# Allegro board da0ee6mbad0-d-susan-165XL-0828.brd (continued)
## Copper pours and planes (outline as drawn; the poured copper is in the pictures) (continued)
GND on IN3 (solid shape): 105.07,56.59 105.7,55.96 105.7,53.9 105.3,53.5 101.39,53.5 99.24,51.35 99.21,51.33 99.19,51.33 99.16,51.33 99.14,51.35 99.12,51.37 99.11,51.54 102.92,55.35 102.92,57.48 103.09,57.48 103.09,57.13 103.12,57.09 103.12,56.69 103.37,56.45 103.71,56.45 103.79,56.53 103.87,56.45 104.21,56.45 104.46,56.69 104.46,57.08 104.5,57.13 104.5,57.48 104.26,57.72 103.91,57.72 103.88,57.69 103.71,57.69 103.67,57.72 103.33,57.72 103.09,57.48 102.92,57.48 102.92,58.08 102.92,58.09 102.93,58.13 102.95,58.16 102.97,58.18 102.99,58.2 103.02,58.22 103.06,58.23 103.09,58.23 103.14,58.22 103.2,58.22 103.26,58.22 103.32,58.23 103.38,58.26 103.44,58.28 103.49,58.32 103.53,58.36 103.57,58.41 103.61,58.46 103.63,58.52 103.65,58.58 103.66,58.64 103.66,58.82 105.07,58.82
GND on IN3 (solid shape): 49.03,57.15 49.12,57.18 49.22,57.15 49.29,57.11 49.37,57.09 49.4,57.09 49.47,57.01 49.47,56.57 49.91,56.12 49.96,56.02 49.91,55.91 49.81,55.68 49.88,55.43 49.88,54.74 49.79,54.6 49.62,54.64 49.36,54.75 49.09,54.65 48.76,54.65 48.76,54.78 49.18,55.2 49.18,56 49.18,56.01 49.18,56.46 49.03,56.61
GND on IN3 (solid shape): 25.02,54.79 25.11,54.94 25.28,54.9 26.23,53.94 26.36,53.94 26.36,53.85 26.35,53.83 26.35,53.41 26.74,53.25 26.75,53.25 26.83,53.25 26.83,53.09 26.77,53.08 26.46,52.73 26.77,52.38 26.83,52.37 26.83,50.06 26.94,49.84 27.18,49.79 27.19,49.79 27.27,49.79 27.27,49.63 27,49.36 26.98,49.35 26.89,49.3 26.82,49.21 26.71,49.12 26.57,49.17 25.02,50.72
GND on IN3 (solid shape): 40.6,81.07 40.73,80.98 40.71,80.81 41.02,80.14 41.32,80.81 41.3,80.98 41.44,81.07 41.63,81.07 41.75,81 41.77,80.87 42.16,80.34 42.55,80.87 42.57,81 42.7,81.07 44.56,81.07 44.85,80.78 44.85,79.57 44.47,79.19 43.49,79.19 43.45,79.23 38.58,79.23 38.17,79.64 38.17,80.78 38.45,81.07
GND on IN3 (solid shape): 68.26,70.29 68.26,69.46 67.79,68.99 66.6,68.99 66.6,69.28 66.43,69.45 63.61,69.45 63.42,69.25 63.42,68.18 63.14,67.9 62.15,67.9 61.84,67.59 61.52,67.59 61.47,67.64 61.33,67.64 60.96,67.68 60.75,67.37 60.73,67.31 60.68,67.29 60.58,67.29 60.58,67.39 60.24,67.74 59.87,67.43 59.86,67.36 58.95,67.36 58.95,67.52 58.99,67.62 59.32,67.78 59.41,68.02 59.41,68.58 59.39,68.69 59.34,68.8 59.32,68.96 59.46,69.04 60.27,69.04 60.27,68.96 60.46,68.65 60.83,68.67 60.85,68.68 60.92,68.68 60.97,68.63 61.2,68.63 61.36,68.8 61.36,68.9 61.98,68.9 62.18,68.7 62.53,68.7 62.77,68.94 62.77,69.29 62.65,69.41 62.8,69.55 62.8,69.9 62.55,70.14 62.51,70.14 62.25,70.39 62.25,70.64 62.38,70.77 67.79,70.77
GND on IN3 (solid shape): 30.77,75.49 30.99,75.28 32.53,75.28 32.74,75.49 32.74,75.54 32.96,75.54 32.96,75.33 32.89,75.26 32.86,75.26 32.56,74.88 32.92,74.55 33.42,74.55 33.51,74.56 33.6,74.59 33.75,74.59 33.82,74.46 33.82,74.27 33.76,74.14 33.62,74.12 33.32,74.1 33.15,73.86 33.14,73.79 32.36,73.79 31.76,74.39 31.75,74.41 31.65,74.53 31.51,74.57 31.01,74.57 30.82,74.49 30.74,74.31 30.74,74.07 30.51,74.07 30.32,73.99 30.24,73.81 30.24,73.65 30.15,73.48 30.17,73.29 30.15,73.15 30.02,73.09 29.89,73.09 29.76,72.96 27.39,72.96 26.86,72.43 26.3,72.43 26.06,72.67 26.06,75.3 26.14,75.44 26.3,75.42 26.56,75.34 26.8,75.44 27.01,75.44 29.54,75.44 30.64,76.54 30.77,76.54
GND on IN3 (solid shape): 25.16,80.76 25.26,80.8 25.36,80.78 25.42,80.74 25.49,80.72 25.61,80.62 25.57,80.47 25.45,80.34 25.45,77.34 25.39,77.22 24.93,77.1 24.79,76.79 24.79,76.18 24.93,75.86 25.39,75.74 25.45,75.62 25.45,72.42 25.64,72.23 25.67,72.06 25.53,71.97 25.46,71.97 25.45,72.03 25.15,72.28 24.89,72 24.89,70.09 25.16,69.81 25.45,70.08 25.45,70.11 26.71,71.37 27.54,71.37 27.54,70.79 27.68,70.65 30.23,70.65 30.37,70.56 30.33,70.39 30.22,70.27 30.22,70.09 29.89,70.09 29.71,69.91 29.71,66.18 29.64,66.05 29.61,65.91 29.61,63.55 29.63,63.45 29.67,63.35 29.7,63.3 29.05,62.65 29.05,59.3 29.47,58.88 30.12,58.88 30.15,58.91 30.24,58.87 30.24,58.36 30.01,58.14 30.01,57.8 27.9,57.8 27.71,57.61 27.71,57.35 27.61,57.2 27.45,57.24 27.38,57.31 27.38,57.34 26.83,57.89 24.84,57.89 24.65,57.7 24.48,57.66 24.39,57.81 24.39,79.99
GND on IN3 (solid shape): outline of 397 points within 18.38,12.3 24.69,32.89
GND on IN3 (solid shape): outline of 644 points within 21.64,34.48 51.35,54.34
GND on IN3 (solid shape): outline of 3811 points within 0.51,0.51 175.29,87.42
GND on GND3 (solid shape): outline of 58666 points within 0.51,0.51 175.29,87.42
GND on IN4 (solid shape): 67.33,60.91 64.41,60.91 64.41,64.62 67.33,64.62
GND on IN4 (solid shape): 68.43,85.41 65.77,85.41 65.77,85.92 68.43,85.92
GND on IN4 (solid shape): 35.56,79.25 33.73,77.42 33.73,77.19 33.75,77.16 33.71,77.07 32.19,77.07 32.19,77.78 33.99,79.58 33.99,79.92 34.04,79.97 35.56,79.97
GND on IN4 (solid shape): 30.24,52.66 30.31,52.48 30.53,52.37 30.55,52.32 30.55,52.03 29.99,52.03 29.9,52.12 29.9,53.6 30.02,53.72 30.24,53.72
GND on IN4 (solid shape): 59.68,56.82 59.68,56.47 59.81,56.34 59.81,56.15 59.72,56.06 59.41,56.06 59.3,56.04 59.21,55.98 59.12,55.89 58.92,55.89 58.85,55.97 58.85,56.8 58.97,56.91 59.14,56.91 59.33,57.11 59.39,57.11
GND on IN4 (solid shape): 88.99,50.55 88.99,47.42 88.88,47.3 88.52,47.3 88.02,47.8 88.02,48.36 87.42,48.96 86.08,48.96 85.93,49.11 85.93,49.57 85.87,49.63 85.83,49.79 85.97,49.89 87.87,49.89 88.62,50.64 88.9,50.64
GND on IN4 (solid shape): 47.25,60.83 47.34,60.97 47.51,60.93 47.81,60.63 47.81,60.25 48.08,59.98 49.77,59.98 49.87,59.94 49.92,59.84 49.92,59.82 49.92,59.73 47.37,59.73 47.25,59.86
GND on IN4 (solid shape): 34.23,52.12 34.23,49.74 33.91,49.42 33.91,49.4 33.87,49.37 32.89,49.37 32.69,49.57 32.69,49.91 32.61,50.11 32.42,50.19 32.39,50.19 31.24,51.34 31.2,51.44 31.23,51.54 31.27,51.61 31.29,51.68 31.29,51.71 31.47,51.89 31.47,52.4 33.95,52.4
GND on IN4 (solid shape): 65.43,80.62 65.6,80.65 65.69,80.51 65.69,76.72 65.64,76.61 65.51,76.57 65.36,76.58 65.22,76.53 65.21,76.52 64.9,76.52 64.42,76.04 64.26,76.01 64.16,76.15 64.16,77.04 64.13,77.07 64.13,77.1 64.1,77.23 64,77.33 64,77.74 63.96,77.78 63.95,77.78 63.68,78.05 63.68,78.17 64,78.49 64,79.19
GND on IN4 (solid shape): 86.63,71.78 86.63,69.81 86.18,69.36 86.18,68.91 86.14,68.81 85.85,68.67 85.77,68.48 85.77,68.12 85.79,68.03 85.83,67.95 85.86,67.85 85.82,67.75 85.43,67.37 85.32,67.32 85.21,67.38 85.18,67.41 85.15,67.44 85.15,68.26 85.16,68.27 85.18,68.47 85.07,68.63 85.07,70.79 84.69,71.17 84.69,71.72 84.82,71.84 86.57,71.84
GND on IN4 (solid shape): 62.34,86.42 62.34,85.81 63.03,84.89 64.1,85.29 64.2,85.29 64.51,84.98 62.87,84.41 61.83,85.81 61.83,85.91 58.15,85.91 58.15,84.84 54.12,84.84 54.12,84.14 51.66,84.14 51.41,84.39 51.38,84.56 51.52,84.65 53.61,84.65 53.61,85.35 57.64,85.35 57.64,86.42 57.64,86.42 62.34,86.42
GND on IN4 (solid shape): outline of 129 points within 12.68,46.31 20.42,54.87
GND on IN4 (solid shape): 97.24,62.72 97.3,62.6 97.3,61.6 97.38,61.4 97.69,61.27 97.74,61.16 97.74,61.11 97.69,61.01 97.59,60.96 97.33,60.68 97.59,60.4 97.69,60.35 97.74,60.25 97.74,59.42 97.74,59.4 97.74,59.01 97.74,59 97.74,58.15 97.74,58.13 97.74,57.74 97.74,57.73 97.74,56.88 97.74,56.86 97.74,56.47 97.74,56.46 97.74,55.61 97.74,55.59 97.74,55.2 97.74,55.19 97.74,54.34 97.74,54.32 97.74,53.93 97.74,53.92 97.74,53.1 97.74,53.08 97.74,52.66 97.74,52.65 97.74,51.83 97.74,51.81 97.74,51.39 97.74,51.38 97.74,50.09 97.64,49.95 97.48,49.98 97.1,50.36 97.1,51.31 97.08,51.35 97.07,51.39 97.08,51.42 97.1,51.46 97.1,51.74 97.08,51.79 97.07,51.82 97.08,51.85 97.1,51.89 97.1,52.58 97.08,52.62 97.07,52.66 97.08,52.69 97.1,52.73 97.1,52.97 97.07,53.01 97.05,53.06 97.07,53.11 97.1,53.15 97.1,53.75 97.08,53.77 97.08,55.42 96.72,55.78 96.72,62.54 96.92,62.74 97.05,62.74 97.08,62.74 97.11,62.75
GND on IN4 (solid shape): 45.96,59.99 46.02,59.92 45.96,59.84 45.79,59.69 45.87,59.47 45.92,59.35 45.87,59.23 45.81,59.16 45.79,59.07 45.77,59.02 45.57,58.94 45.48,58.74 45.43,58.72 45.24,58.58 45.29,58.35 45.29,58.22 45.22,58.15 45.14,58.15 44.85,58.08 44.91,57.79 44.94,57.77 44.94,57.42 44.83,57.3 44.42,57.71 44.42,58.32 44.44,58.34 44.46,58.39 44.48,58.44 44.52,58.53 44.61,58.58 44.74,58.64 44.8,58.78 44.82,58.83 44.87,58.86 45.07,59 45,59.23 44.95,59.35 45,59.47 45.06,59.54 45.08,59.63 45.1,59.68 45.16,59.71 45.29,59.76 45.36,59.88 45.37,59.95 45.8,59.95 45.87,60.02
GND on IN4 (solid shape): outline of 176 points within 31.28,71.57 35.74,76.55
GND on IN4 (solid shape): outline of 197 points within 30.77,52.92 35.74,57.9
GND on IN4 (solid shape): 44.98,71.07 44.98,70.7 45.24,70.44 45.4,70.44 45.53,70.36 45.53,70.21 45.51,70.16 45.51,70.11 45.48,70.06 45.43,70.03 45.22,69.82 45.43,69.61 45.48,69.59 45.57,69.39 45.77,69.3 45.79,69.25 45.81,69.16 45.87,69.09 45.92,68.97 45.79,68.69 45.92,68.41 45.87,68.29 45.81,68.22 45.79,68.13 45.77,68.08 45.71,68.05 45.63,68.03 45.56,67.98 45.45,67.94 45.34,67.98 45.29,68.03 45.25,68.14 45.3,68.25 45.35,68.48 45.16,68.62 45.1,68.64 45.08,68.69 45.06,68.78 45,68.85 44.95,68.97 45,69.09 45.07,69.32 44.87,69.47 44.82,69.49 44.8,69.54 44.74,69.68 44.61,69.75 44.52,69.79 44.48,69.88 44.46,69.94 44.44,69.99 44.42,70.01 44.42,71.33 44.48,71.43 44.62,71.43
GND on IN4 (solid shape): outline of 131 points within 49.7,60.66 53.89,66.78
GND on IN4 (solid shape): 50.04,71.27 50.32,71 50.32,70.96 50.37,70.81 50.52,70.74 50.58,70.72 50.6,70.67 50.81,70.46 51.02,70.67 51.05,70.72 51.1,70.74 51.17,70.75 51.23,70.79 51.33,70.82 51.43,70.77 52.05,70.16 52.09,70.06 52.06,69.95 52.03,69.89 52.01,69.83 51.99,69.77 51.94,69.75 51.82,69.71 51.74,69.61 51.72,69.56 51.6,69.56 51.58,69.61 51.55,69.66 51.51,69.7 51.46,69.82 51.51,69.94 51.38,70.32 51.24,69.94 51.3,69.82 51.24,69.7 51.21,69.67 51.09,69.62 50.98,69.67 50.9,69.73 50.82,69.75 50.76,69.77 50.74,69.83 50.53,70.03 50.32,69.83 50.29,69.77 50.24,69.75 50.15,69.73 50.08,69.67 49.96,69.62 49.84,69.67 49.81,69.7 49.76,69.82 49.81,69.94 49.87,70.01 49.89,70.1 49.91,70.15 49.97,70.17 50.17,70.39 49.97,70.6 49.91,70.62 49.89,70.67 49.87,70.76 49.82,70.83 49.8,70.85 49.8,71 49.6,71.2 49.6,71.27 49.75,71.42 49.75,71.67 49.81,71.71 49.86,71.76 50.04,71.76
GND on IN4 (solid shape): outline of 86 points within 55.98,57.45 65.55,60.16
GND on IN4 (solid shape): outline of 266 points within 83.28,72.34 90.45,78.51
GND on IN4 (solid shape): outline of 377 points within 42.39,76.81 56.04,81.74
GND on IN4 (solid shape): outline of 451 points within 99.64,49.61 108.63,60.73
GND on IN4 (solid shape): outline of 763 points within 79.88,53.67 97.76,76.17
GND on IN4 (solid shape): outline of 930 points within 66.58,64.56 84.43,80.51
GND on IN4 (solid shape): outline of 1020 points within 46.08,60.22 52.56,69.74
GND on IN4 (solid shape): outline of 1997 points within 51.18,59.51 64.56,78.51
GND on IN4 (solid shape): outline of 13878 points within 0.51,0.51 175.29,87.42
VDD_1V8_AUDIO on BOTTOM (solid shape): 113.81,80.93 113.81,80.7 113.61,80.49 113.61,79.78 112.29,79.78 112.16,79.91 112.16,80.67 112.54,81.05 113.69,81.05
VDDCORE on BOTTOM (solid shape): 31.38,24.04 31.38,23.26 31.9,22.73 31.9,22.15 31.87,22.12 31.31,22.12 31.26,22.18 31.26,22.79 30.5,23.55 30.5,24.03 30.63,24.16 31.26,24.16
VIN_LDO on BOTTOM (solid shape): 150.39,83.19 150.39,81.54 150.26,81.41 149.5,81.41 149.25,81.66 148.74,81.66 148.61,81.79 148.61,83.19 148.74,83.31 150.26,83.31
24192_PMID on BOTTOM (solid shape): 101.11,57.74 101.11,56.57 101.9,55.78 102.71,55.78 102.71,55.5 101.65,55.5 100.73,56.41 100.17,56.41 100.17,57.76 101.09,57.76
24192_SW on BOTTOM (solid shape): 102.74,54.21 102.74,54 101.88,54 101.88,53.78 102.74,53.78 102.74,53.19 101.95,52.4 101.95,48.01 101.52,47.58 99.41,47.58 99.23,47.75 99.23,53.52 99.56,53.85 100.58,53.85 101.01,54.28 102.66,54.28
63020_L1 on BOTTOM (solid shape): 103.78,73.43 103.78,72.28 104.39,71.68 104.55,71.68 104.56,71.67 105.67,71.67 105.69,71.65 105.69,71.4 105.66,71.37 100.12,71.37 99.84,71.65 99.84,72.22 99.85,72.25 99.87,72.26 100.01,72.54 99.87,72.82 99.85,72.84 99.84,72.86 99.84,73.43 100.1,73.68 103.53,73.68
63020_L2 on BOTTOM (solid shape): 104.74,70.66 105.7,70.66 105.71,70.65 105.71,70.42 105.66,70.37 104.39,70.37 104.16,70.14 104.16,67.48 103.91,67.22 100.1,67.22 99.84,67.48 99.84,70.4 100.12,70.68 104.72,70.68
63020_VINA on BOTTOM (solid shape): 110,70.69 110,69.37 109.88,69.24 109.37,69.24 109.12,69.5 109.12,70.77 109.01,70.87 108.02,70.87 107.99,70.88 107.97,70.92 107.97,71.12 107.99,71.16 108.02,71.17 109.52,71.17
+V_SFR0 on TOP (solid shape): 49.6,69.19 49.6,68.35 50.97,66.98 50.97,60.76 50.85,60.63 50.85,57.13 50.97,57 56.38,57 60.37,53.01 60.37,51.64 60.7,51.31 61.41,51.31 61.82,51.72 61.82,58.35 61.54,58.62 61.54,59.95 61.85,60.25 61.85,60.73 62.35,60.73 62.35,60.02 62.13,59.79 62.13,58.88 62.38,58.62 62.38,51.44 61.77,50.83 59.99,50.83 59.64,51.18 59.64,52.66 55.9,56.39 51.86,56.39 51.51,56.03 51.51,55.17 50.54,55.17 49.91,55.81 49.91,56.47 50.36,56.92 50.36,66.73 48.97,68.12 48.97,69.17 49.07,69.27 49.53,69.27
+V_SFR0 on BOTTOM (solid shape): 50.32,56.67 50.35,56.63 50.39,56.59 50.56,56.42 50.56,56.41 50.6,56.3 50.69,56.22 50.72,56.21 50.72,54.89 50.47,54.64 50.47,54.26 50.42,54.21 49.88,54.21 49.83,54.26 49.83,54.76 50.24,55.17 50.24,56.07 50.24,56.08 50.21,56.31 50.02,56.45 49.98,56.46 49.98,56.55 50.02,56.56 50.12,56.61 50.19,56.69 50.2,56.72 50.26,56.72
+V_SFR1 on TOP (solid shape): 62.43,64.95 62.43,64.49 62.38,64.44 61.82,64.44 61.44,64.06 60.58,64.06 60.52,64.11 60.52,64.92 60.63,65.03 62.35,65.03
+V_SFR1 on BOTTOM (solid shape): 61.69,65.2 61.69,64.87 61.36,64.87 61.22,65.01 59.72,65.01 59.48,65.25 59.48,65.35 59.51,65.36 59.56,65.4 59.6,65.46 61.44,65.46
+V_SFR1 on IN1 (solid shape): outline of 500 points within 47.57,63.43 61.03,69.34
+V_VCC on BOTTOM (solid shape): 84.76,76.61 84.7,76.48 84.68,76.34 85.11,75.9 85.54,76.34 85.53,76.48 85.46,76.61 86.38,76.61 86.69,76.3 86.69,73.86 86.51,73.69 73.43,73.69 73.3,73.56 73.3,72.06 73.81,71.55 73.81,64.54 73.63,64.37 71.98,64.37 71.9,64.29 71.37,64.29 71.32,64.34 71.32,64.77 71.35,64.8 71.35,64.95 71.24,65.05 71.24,68.53 67.46,72.32 67.46,75.16 67.59,75.29 71.12,75.29 71.24,75.41 71.24,76.38 71.47,76.61
+V_VCC on BOTTOM (solid shape): outline of 175 points within 49.73,62.59 51.94,65.25
+V_VCC on BOTTOM (solid shape): outline of 548 points within 49.68,65.86 55.24,74.09
+V_VCC on IN2 (solid shape): 52.65,69.17 52.65,68.91 52.6,68.86 51.86,68.86 51.74,68.73 51.74,66.14 51.76,66.12 51.76,65.89 51.69,65.86 51.34,65.86 51.33,65.86 51.17,65.86 51.1,65.79 51.1,65.36 51.2,65.25 51.66,65.25 51.76,65.15 51.76,62.77 51.61,62.61 50.9,62.61 50.82,62.69 50.82,64.02 50.8,64.04 50.8,64.14 50.16,64.77 50.16,67.41 50.69,67.93 50.69,69.13 50.85,69.29 52.52,69.29
+V_VCC on SVCC2 (solid shape): 70.51,77.01 70.51,68.59 70.02,68.1 61.74,68.1 61.65,68.08 61.56,68.03 61.26,67.72 60.22,67.72 60.12,67.7 60.04,67.64 59.61,67.21 58.42,67.21 57.61,68.03 57.52,68.08 57.43,68.1 53.49,68.1 53.39,68.08 53.31,68.03 53.05,67.77 53,67.69 52.98,67.59 52.98,64.65 51.91,63.58 51.86,63.5 51.84,63.4 51.84,62.74 51.6,62.51 48.31,62.51 48.16,62.67 48.16,77.14 48.39,77.37 70.15,77.37
+V_VCC on IN3 (solid shape): outline of 105 points within 49.73,62.61 52.93,71.1
+V_VCC on IN4 (solid shape): outline of 246 points within 49.73,62.59 52.9,71.38
+V_VNN on BOTTOM (solid shape): 73.81,63.5 73.81,62.39 73.81,53.04 74.29,52.55 84.53,52.55 84.63,52.45 84.63,51.64 84.5,51.51 84.18,51.51 83.8,51.13 82.52,51.13 81.96,50.57 73.81,50.57 73.3,51.08 71.27,51.08 70.89,51.46 70.89,51.84 70.61,52.12 66.98,52.12 66.86,52.23 66.86,52.73 66.87,52.74 66.87,54.86 67.01,55 68.85,55 69.01,54.84 69.01,53.85 69.16,53.7 70.38,53.7 70.91,54.23 70.91,59.54 71.32,59.95 71.32,62.94 71.4,63.02 71.75,63.02 72.44,63.7 73.61,63.7
+V_VNN on BOTTOM (solid shape): 59.4,58.93 59.48,58.84 59.59,58.79 59.6,58.78 59.86,58.52 60.27,58.52 60.89,57.91 60.89,57.86 60.94,57.48 61.31,57.37 61.34,57.37 61.39,57.32 61.39,55.35 60.47,54.43 56.31,54.43 55.98,54.76 55.98,56.19 55.89,56.27 55.89,56.28 55.83,56.36 55.75,56.42 55.72,56.44 55.72,56.57 55.75,56.59 55.8,56.62 55.84,56.67 55.85,56.69 55.96,56.69 55.97,56.67 56.04,56.6 56.14,56.56 56.2,56.52 56.22,56.45 56.48,56.19 56.72,56.47 56.72,56.47 56.76,56.52 56.87,56.57 56.95,56.66 56.96,56.69 57.04,56.69 57.36,56.38 57.36,56.37 57.41,56.29 57.48,56.23 57.5,56.21 57.5,55.88 57.6,55.78 59.03,55.78 59.92,56.67 59.92,57.61 59.74,57.79 59.61,57.79 59.51,57.89 59.51,58 59.62,58.29 59.38,58.47 59.36,58.47 59.3,58.53 59.3,58.54 59.24,58.63 59.16,58.7 59.13,58.71 59.13,58.86 59.16,58.87 59.21,58.91 59.26,58.96 59.39,58.96
+V_VNN on BOTTOM (solid shape): outline of 773 points within 48.64,60.2 54.69,67.64
+V_VNN on SVCC2 (solid shape): 58.13,66.78 58.22,66.72 58.32,66.7 59.71,66.7 59.81,66.72 59.89,66.78 60.33,67.21 61.36,67.21 61.46,67.23 61.54,67.28 61.85,67.59 70.27,67.59 70.51,67.36 70.51,64.62 70.54,64.49 70.63,64.4 70.63,64.16 70.65,64.11 70.68,64.06 70.76,63.98 70.76,61.93 70.56,61.72 70.52,61.68 70.51,61.62 70.51,50.58 70.38,50.45 61.72,50.45 61.55,50.38 61.47,50.22 61.39,50.22 61.33,50.2 61.29,50.17 61.06,49.94 55.95,49.94 55.75,50.15 55.69,50.35 55.5,50.45 51.18,50.45 48.54,53.09 48.54,60.1 48.52,60.2 48.46,60.28 48.16,60.59 48.16,61.86 48.29,62 51.71,62 51.81,62.02 51.89,62.08 52.27,62.46 52.33,62.54 52.35,62.64 52.35,63.29 53.42,64.36 53.47,64.45 53.49,64.54 53.49,67.48 53.6,67.59 57.32,67.59
+V_VNN on IN3 (solid shape): outline of 403 points within 48.59,60.22 55.11,67.77
+V_VNN on IN4 (solid shape): outline of 193 points within 48.61,60.2 54.69,67.63
+VBL_LCM on TOP (solid shape): 52.6,37.75 52.6,36.6 52.47,36.48 51.58,36.48 50.95,37.11 50.95,37.87 51.08,38 52.35,38
+VBL_LCM on BOTTOM (solid shape): 52.73,37.11 52.73,36.35 52.66,36.29 52.66,35.22 52.41,35.22 52.41,36.02 52.4,36.03 52.09,36.03 52.07,36.01 52.07,35.22 51.8,35.22 51.8,36.67 51.84,36.7 51.84,37.11 52.09,37.36 52.47,37.36
+VBL_LCM on BOTTOM (solid shape): 69.62,46.89 69.62,38.74 69.67,38.69 70.71,38.69 70.91,38.48 70.91,35.99 70.25,35.33 68.98,35.33 68.73,35.59 68.73,36.48 68.35,36.86 68.35,37.87 67.71,38.51 67.71,46.89 67.97,47.14 69.36,47.14
+VHDMI on IN2 (solid shape): 88.8,66.7 88.8,66.47 88.47,66.32 88.47,65.97 88.19,65.69 87.96,65.69 87.8,65.84 87.8,66.17 88.13,66.5 88.18,66.52 88.22,66.55 88.4,66.73 88.77,66.73
+VLPC on BOTTOM (solid shape): 54.86,56.67 54.86,56.66 54.91,56.59 54.99,56.54 55,56.53 55.08,56.45 55.09,56.43 55.13,56.3 55.24,56.21 55.27,56.19 55.27,54.87 55.42,54.71 55.42,53.87 55.5,53.8 55.52,53.8 55.55,53.77 55.55,53.27 54.99,53.27 54.86,53.39 54.86,56.2 54.61,56.46 54.61,56.57 54.65,56.61 54.68,56.66 54.7,56.69 54.84,56.69
+VREF_DQ0 on TOP (solid shape): 79.14,58.4 79.14,56.97 79.02,56.85 78.15,56.85 78.05,56.95 78.05,58.37 78.11,58.43 79.1,58.43
+VREF_DQ1 on TOP (solid shape): 41.27,55.42 39.01,55.42 39.01,55.96 41.27,55.96
+VREF_DQ1 on TOP (solid shape): 79.12,55.91 79.12,53.93 79.02,53.82 78.23,53.82 78.13,53.93 78.13,55.93 78.15,55.96 79.07,55.96
+VRTC on IN1 (solid shape): outline of 356 points within 53.72,70.16 65.71,76.48
+VSDIO on BOTTOM (solid shape): 54.4,53.75 54.44,53.73 54.45,53.7 54.45,53.09 54.61,52.94 57.6,52.94 57.73,52.81 57.73,52.53 57.58,52.38 54.17,52.38 53.97,52.58 53.97,53.7 53.99,53.73 54.02,53.75
+VSDIO_SOC on BOTTOM (solid shape): 53.54,56.21 53.54,55.3 53.54,54.94 53.62,54.87 53.62,53.32 53.54,53.24 52.98,53.24 52.98,53.8 53.24,54.05 53.24,54.71 53.18,54.76 53.18,56.21 53.19,56.22 53.25,56.26 53.29,56.31 53.44,56.31
+VSYS on TOP (solid shape): 150.64,73.56 150.64,71.78 148.83,71.78 148.76,71.85 148.76,72.68 148.62,72.82 148.61,72.82 148.61,73.69 148.74,73.81 150.39,73.81
+VSYS on BOTTOM (solid shape): 79.02,63.02 79.02,62.16 78.51,61.65 75.82,61.65 75.56,61.9 75.56,63.02 75.69,63.15 78.89,63.15
+VSYS on BOTTOM (solid shape): 108.94,77.37 108.94,76.18 108.81,76.05 106.83,76.05 106.65,76.23 106.65,77.37 106.71,77.43 108.87,77.43
+VSYS on BOTTOM (solid shape): 94.54,72.06 94.54,68.63 94.38,68.48 92.99,68.48 92.86,68.61 92.86,70.44 93.8,71.38 93.8,72.06 93.93,72.19 94.41,72.19
+VSYS on BOTTOM (solid shape): 88.95,61.7 90.32,61.7 90.37,61.65 90.37,60.94 90.31,60.87 89.32,60.87 88.39,61.8 87.22,61.8 87.14,61.88 87.14,62.03 87.19,62.08 88.57,62.08
+VSYS on BOTTOM (solid shape): 91.74,65.94 91.74,65.05 91.69,65 89.28,65 88.11,63.83 86.41,63.83 86.36,63.88 86.36,64.03 86.41,64.09 87.83,64.09 89.71,65.97 91.72,65.97
+VSYS on BOTTOM (solid shape): 22.93,26.37 23.52,26.37 23.62,26.27 23.62,25.66 23.75,25.53 23.88,25.53 24,25.41 24,24.47 23.92,24.39 22.09,24.39 20.95,25.53 20.06,25.53 19.76,25.83 19.76,27.61 19.94,27.79 21.51,27.79
+VSYS on BOTTOM (solid shape): 77.64,69.32 77.64,68.53 81.3,64.87 81.76,64.87 81.81,64.82 81.81,64.67 81.76,64.62 80.9,64.62 78.69,66.83 75.97,66.83 75.79,67.01 75.79,69.39 75.87,69.47 77.49,69.47
+VSYS on BOTTOM (solid shape): 86.53,68.61 86.53,68.07 85.42,66.96 85.42,65.84 85.37,65.79 85.19,65.79 85.14,65.84 85.14,67.31 85.82,68 85.82,68.61 85.9,68.68 86.46,68.68
+VSYS on BOTTOM (solid shape): 82.55,71.55 82.55,67.08 83,66.63 83,65.86 82.98,65.84 82.75,65.84 82.72,65.86 82.73,65.95 82.72,66 82.72,66.27 79.93,69.06 79.93,71.6 80.01,71.68 82.42,71.68
+VSYS on BOTTOM (solid shape): 85.04,60.45 85.04,59.18 85.19,59.03 85.54,59.03 86.64,57.94 86.64,57.1 86.53,57 85.77,57 85.67,57.1 85.67,57.99 84.73,58.93 84.73,60.48 84.76,60.5 84.99,60.5
+VSYS on BOTTOM (solid shape): 83.03,60.48 83.03,59.54 82.52,59.03 82.52,54.66 82.39,54.54 80.08,54.54 79.96,54.66 79.96,57.46 81.28,58.78 81.66,58.78 82.72,59.84 82.72,60.48 82.75,60.5 83,60.5
+VSYS on BOTTOM (solid shape): 85.83,60.85 85.83,59.58 87.7,57.71 87.7,57.05 87.65,57 86.84,57 86.74,57.1 86.74,57.99 85.53,59.2 85.53,60.85 85.57,60.89 85.8,60.89
+VSYS on BOTTOM (solid shape): 104.17,52.5 104.4,52.5 104.4,53.34 104.62,53.34 104.67,53.29 104.67,52.33 106.68,50.32 110.77,50.32 110.89,50.19 110.89,46.89 110.64,46.64 107.85,46.64 107.72,46.76 106.14,46.76 105.84,47.07 103.73,47.07 103.45,47.35 103.45,50.6 103.91,51.06 103.91,53.29 103.96,53.34 104.17,53.34
+VSYS on BOTTOM (solid shape): 88.46,69.17 88.46,68.51 87.59,67.63 86.88,67.63 85.82,66.57 85.82,66.5 85.82,65.84 85.82,65.84 85.82,65.46 85.77,65.41 85.59,65.41 85.54,65.46 85.54,66.93 86.66,68.05 86.66,68.61 86.74,68.68 87.12,68.68 87.65,69.22 88.41,69.22
+VSYS on BOTTOM (solid shape): 81.68,61.69 81.76,61.7 81.81,61.65 81.81,61.47 81.73,61.39 81.67,61.4 81.63,61.39 81.28,61.39 79.91,60.02 79.91,59.74 77.47,57.3 77.47,56.64 77.39,56.57 76.04,56.57 75.87,56.75 75.87,59.06 75.99,59.18 78.53,59.18 81.05,61.7 81.63,61.7
+VSYS on BOTTOM (solid shape): 87.83,71.63 87.83,69.57 87.04,68.78 85.09,68.78 84.91,68.61 84.91,67.79 84.63,67.51 84.63,66 84.62,65.95 84.63,65.86 84.6,65.84 84.35,65.84 84.32,65.86 84.33,65.95 84.32,66 84.32,68.91 84.78,69.37 86.38,69.37 86.79,69.78 86.79,71.63 86.92,71.76 87.7,71.76
+VSYS on IN1 (solid shape): outline of 132 points within 108.15,46.48 154.07,75.8
+VSYS on IN2 (solid shape): 87.78,57.76 87.78,57.13 87.73,57.08 85.72,57.08 85.67,57.13 85.67,57.76 85.75,57.84 87.7,57.84
+VSYS on IN2 (solid shape): 90.12,65.99 90.45,65.99 90.73,65.71 91.44,65.71 91.56,65.58 91.56,65.23 91.51,65.18 89.91,65.18 89.81,65.28 89.81,65.89 89.94,66.02 90.09,66.02
+VSYS on SVCC2 (solid shape): outline of 116 points within 14.12,8.66 111.91,78.77
+VSYS on IN3 (solid shape): 77.42,69.39 77.42,66.93 77.37,66.88 76.73,66.88 76.57,67.04 76.57,69.41 76.63,69.47 77.34,69.47
+VSYS on IN3 (solid shape): 77.52,62.61 77.52,61.6 77.49,61.57 76.1,61.57 75.99,61.67 75.99,62.43 76.25,62.69 77.44,62.69
+VSYS on IN3 (solid shape): 87.7,57.76 87.7,57.1 87.68,57.08 85.75,57.08 85.7,57.13 85.7,57.76 85.72,57.79 87.68,57.79
+VSYS on IN3 (solid shape): 88.08,71.43 88.08,70.73 87.83,70.48 86.82,70.48 86.81,70.49 86.81,71.5 86.89,71.58 87.93,71.58
+VSYS on IN3 (solid shape): 91.69,65.76 91.69,65.05 91.64,65 89.79,65 89.71,65.08 89.71,65.71 89.81,65.81 91.64,65.81
+VSYS on IN3 (solid shape): 94.23,70.72 94.23,69.04 94.21,69.01 93.39,69.01 93.34,69.06 93.34,70.72 93.39,70.77 94.18,70.77
+VSYS on IN3 (solid shape): 82.32,55.88 82.32,54.81 82.22,54.71 79.96,54.71 79.93,54.74 79.93,55.88 80.01,55.96 82.24,55.96
+VSYS on IN3 (solid shape): 77.39,59.13 77.39,56.16 77.29,56.06 76.12,56.06 76.04,56.14 76.04,58.5 76.73,59.18 77.34,59.18
+VSYS on IN3 (solid shape): 75.71,53.09 75.71,49.2 75.64,49.13 73.4,49.13 73.33,49.2 73.33,49.79 73.58,50.04 73.99,50.04 74.11,50.17 74.11,51.97 74.32,52.17 74.32,52.96 74.57,53.21 75.59,53.21
+VSYS on IN3 (solid shape): 82.47,71.4 82.51,71.39 82.52,71.35 82.52,71.12 81.68,70.28 80.05,70.28 80.05,70.29 80.03,70.29 79.96,70.36 79.96,70.92 80.24,71.2 80.82,71.2 81.02,71.4
+VSYS_V3.3A on BOTTOM (solid shape): 110.51,78.34 110.51,76.86 110.39,76.73 109.93,76.73 109.75,76.91 109.75,77.4 109.5,77.65 106.17,77.65 106.07,77.55 106.07,76.58 106.32,76.33 106.32,74.45 105.71,73.84 105.71,71.93 105.65,71.87 104.58,71.87 104.04,72.42 104.04,73.59 103.68,73.94 102.38,73.94 102,74.32 102,77.4 103.2,78.59 110.26,78.59
+VSYS_V3.3A on IN4 (solid shape): outline of 122 points within 109.75,69.37 111.15,77.5
BAT- on BOTTOM (solid shape): 110.89,45.32 110.89,42.5 110.77,42.37 109.34,42.37 109.34,45.54 109.74,45.54 109.77,45.57 110.64,45.57
BAT- on BOTTOM (solid shape): 116.05,41.99 116.05,38.46 116,38.41 113.53,38.41 113.29,38.65 113.29,41.98 113.56,42.24 115.8,42.24
BAT- on IN4 (solid shape): outline of 245 points within 109.24,38.74 115.31,45.54
CBUCK_OUT on BOTTOM (solid shape): 153.44,82.91 153.44,82.4 153.69,82.15 154.07,82.15 154.33,81.89 154.33,81.51 154.2,81.38 153.95,81.38 153.79,81.54 151.28,81.54 151.03,81.79 151.03,83.16 151.15,83.29 153.06,83.29
CHG_AGND on BOTTOM (solid shape): 108.94,56.69 108.94,55.5 108.84,55.4 108.25,55.4 108.2,55.45 108.2,56.77 108.25,56.82 108.81,56.82
CHG_AGND on BOTTOM (solid shape): 108.96,54.92 108.96,54.66 108.84,54.54 108.84,53.7 108.76,53.62 108.3,53.62 108.23,53.7 108.23,54.99 108.28,55.04 108.84,55.04
CHG_AGND on IN2 (solid shape): 101.22,55.65 101.22,55.17 102.87,53.52 106.42,53.52 106.6,53.7 106.6,55.3 106.68,55.37 108.4,55.37 108.51,55.27 108.51,54.76 106.7,52.96 102.49,52.96 100.48,54.97 100.48,55.81 100.66,55.98 100.89,55.98
CHG_AGND on IN3 (solid shape): 109.04,58.55 109.04,58.22 108.28,57.46 108.28,56.67 108.91,56.03 108.91,55.68 108.76,55.53 108.76,55.07 108.89,54.94 108.89,54.76 108.82,54.69 108.48,54.69 108.19,54.41 107.95,54.41 107.72,54.64 107.72,57.58 108.73,58.6 108.99,58.6
CPU_VREF on TOP (solid shape): 42.11,64.01 42.87,64.01 42.95,63.93 42.95,63.63 42.24,63.63 42.16,63.7 40.41,63.7 40.41,64.38 40.51,64.48 41.64,64.48
DBVDD on BOTTOM (solid shape): 112.98,73.13 113.82,73.13 113.85,73.1 114.86,73.1 114.88,73.08 114.88,72.9 113.28,72.9 113.05,72.67 111.15,72.67 111.02,72.8 111.02,73.43 111.15,73.56 112.54,73.56
DCIN_5V_IN on BOTTOM (solid shape): 145.82,78.61 145.82,76.02 146.07,75.77 147.9,75.77 148.1,75.57 148.1,74.02 147.9,73.81 145.59,73.81 145.59,75.19 145.54,75.24 144.46,75.24 144.32,75.38 144.32,78.67 144.42,78.77 145.67,78.77
DCIN_5V_IN on IN4 (solid shape): 146.5,77.12 146.5,76.48 146.71,76.28 147.62,76.28 147.88,76.02 147.88,74.19 147.67,73.99 145.56,73.99 145.54,74.02 145.54,75.06 145.46,75.13 144.85,75.13 144.55,75.44 144.55,77.24 144.65,77.34 146.28,77.34
HDMI_VL on TOP (solid shape): 79.83,75.11 79.24,75.11 79.14,75.21 70.84,75.21 70.84,75.49 79.22,75.49 79.3,75.57 79.83,75.57
HP_AGND on BOTTOM (solid shape): 140,76.3 140,75.72 140.39,75.33 140.39,73.67 140.15,73.43 138.68,73.43 138.6,73.51 138.6,75.2 138.89,75.2 138.89,73.8 139.06,73.64 139.96,73.64 140.1,73.78 140.1,75.1 139.96,75.25 139.94,75.26 138.95,75.26 138.89,75.2 138.6,75.2 138.6,75.36 138.88,75.64 139.19,75.64 139.29,75.74 139.29,76.28 139.34,76.33 139.98,76.33
HP_L1 on BOTTOM (solid shape): 118.59,70.17 118.59,69.14 119.33,68.4 119.33,68.1 119.3,68.07 118.67,68.07 118.6,68.01 117.87,68.01 117.85,68.02 117.85,68.45 118.36,68.96 118.4,69.13 118.4,70.19 118.41,70.21 118.56,70.21
HP_OUT_L on BOTTOM (solid shape): 119.28,67.59 119.28,67.1 119.15,66.97 119.15,66.34 119.28,66.21 119.28,65.56 119.23,65.52 118.77,65.52 118.77,67.57 118.84,67.64 119.22,67.64
HP_OUT_R on BOTTOM (solid shape): 121.18,67.55 121.18,65.56 121.05,65.43 120.6,65.43 120.56,65.47 120.56,66.08 120.67,66.19 120.67,66.96 120.55,67.08 120.55,67.59 120.59,67.63 121.1,67.63
HP_R1 on BOTTOM (solid shape): 119.39,70.21 119.39,69.2 119.58,69.01 121.05,69.01 121.18,68.89 121.18,68.18 121.05,68.05 120.44,68.05 120.29,67.9 119.71,67.9 119.61,68 119.61,68.56 119.21,68.95 119.21,70.23 119.38,70.23
HPGND on IN3 (solid shape): 135.42,74.93 135.56,74.84 135.52,74.67 135.48,74.63 126.48,74.63 126.34,74.72 126.37,74.89 126.42,74.93
I2C_VIO on TOP (solid shape): 81.1,66.04 81.1,64.51 80.01,63.41 80.01,62.84 79.78,62.61 78.66,62.61 78.53,62.74 78.53,63.96 78.58,64.01 78.98,64.01 79.91,64.93 79.91,66.02 80.06,66.17 80.97,66.17
I2C_VIO on IN1 (solid shape): 83.16,66.07 83.16,65.64 83.11,65.58 79.96,65.58 79.91,65.64 79.91,66.12 79.96,66.17 83.05,66.17
PMIC_AGND on IN2 (solid shape): 86.28,65.69 86.28,61.72 86.97,61.04 87.6,61.04 87.63,61.01 87.63,60.48 87.58,60.43 86.51,60.43 86.46,60.48 86.46,60.94 85.87,61.52 85.87,65.69 85.92,65.74 86.23,65.74
SPK_LN on BOTTOM (solid shape): 114.42,75.13 114.89,75.13 114.89,74.9 113.89,74.9 113.59,75.21 113.38,75.21 113.23,75.36 113.23,75.67 113.43,75.87 113.69,75.87
SPK_LN on BOTTOM (solid shape): 131.92,77.19 131.92,76.1 131.87,76.05 131.21,76.05 131.16,76.1 131.16,77.19 131.37,77.4 131.72,77.4
SPK_LP on BOTTOM (solid shape): 115.4,76.39 115.4,75.4 115.34,75.34 114.86,75.34 114.45,75.74 114.45,76.28 114.61,76.44 115.35,76.44
SPK_LP on BOTTOM (solid shape): 133.7,77.19 133.7,76.1 133.65,76.05 132.99,76.05 132.94,76.1 132.94,77.14 133.19,77.4 133.5,77.4
SPK_RP on BOTTOM (solid shape): 113.86,73.9 114.83,73.9 114.83,73.7 113.89,73.7 113.86,73.68 113.86,73.66 113.64,73.43 112.93,73.43 112.8,73.56 112.8,73.84 112.9,73.94 113.81,73.94
SPKVDD on BOTTOM (solid shape): 113.74,79.12 113.74,77.88 114.25,77.37 115.21,77.37 115.68,76.9 115.68,76.77 115.78,76.67 115.78,75.44 115.62,75.44 115.59,75.46 115.59,76.48 115.21,76.86 113.43,76.86 113.18,76.61 113.18,75.97 112.98,75.77 112.98,74.5 113.15,74.32 113.81,74.32 113.83,74.3 114.83,74.3 114.83,74.1 113.84,74.1 113.83,74.09 112.87,74.09 112.59,74.37 112.19,74.37 112.04,74.53 112.04,77.98 112.44,78.39 112.65,78.39 112.72,78.46 112.72,79.2 112.8,79.27 113.59,79.27
V_GPS_1V8 on BOTTOM (solid shape): 29.92,20.73 29.95,20.71 29.97,20.68 29.97,20.3 29.82,20.14 29.21,20.14 29.16,20.09 29.16,17.25 29.12,17.22 28.65,17.22 28.62,17.25 28.62,20.73
V_GPS_3V3 on BOTTOM (solid shape): 29.16,16.51 29.33,16.33 30.91,16.33 30.98,16.26 30.98,15.9 30.91,15.83 28.72,15.83 28.65,15.9 28.65,16.94 29.16,16.94
V_GPS_3V3 on BOTTOM (solid shape): 33.52,23.17 33.52,22.63 33.63,22.53 34.11,22.53 34.16,22.48 34.16,22.02 34.11,21.97 33.5,21.97 32.92,22.56 32.92,23.17 32.97,23.22 33.47,23.22
VD_VBUS_CON on TOP (solid shape): outline of 394 points within 100.66,56.49 152.17,84.43
VD_VBUS_CON on BOTTOM (solid shape): 145.54,81.71 145.54,79.22 145.39,79.07 144.42,79.07 144.17,78.82 144.17,75.97 143.91,75.72 142.39,75.72 142.26,75.85 142.26,81.46 142.64,81.84 145.41,81.84
VD_VBUS_CON on BOTTOM (solid shape): 103.55,59.41 103.55,57.68 103.17,57.3 103.17,56.75 102.71,56.29 102.71,56.06 102.7,56.02 102.66,56.01 101.88,56.01 101.32,56.57 101.32,57.86 101.22,57.96 100.94,57.96 100.81,58.09 100.81,59.64 100.91,59.74 103.22,59.74
VD_VBUS_CON on IN1 (solid shape): outline of 428 points within 100.81,56.47 133.5,84.1
VREF25 on IN1 (solid shape): outline of 99 points within 81.35,64.03 86.94,66.91
VREF25 on IN2 (solid shape): 83.72,66.5 83.72,66.02 84.05,65.69 84.05,65 83.79,64.75 83.21,64.75 83.03,64.57 83.03,64.03 83.31,63.76 84.48,63.76 85.57,62.66 85.57,61.47 85.39,61.29 85.09,61.29 84.83,61.55 84.83,62.64 84.07,63.4 81.53,63.4 81.33,63.6 81.33,64.39 81.45,64.52 82.24,64.52 83.31,65.58 83.31,66.32 83.11,66.52 82.75,66.52 82.7,66.57 82.7,66.85 82.75,66.91 83.31,66.91
VS_BAT_R on BOTTOM (solid shape): 107.82,53.26 107.82,52.63 108.18,52.27 108.86,52.27 109.06,52.48 109.06,52.95 109.22,53.1 109.97,53.1 110.64,52.43 110.64,50.75 110.51,50.62 109.14,50.62 109.09,50.57 106.75,50.57 104.9,52.43 104.9,53.27 104.97,53.34 107.73,53.34
VS_BAT_R on BOTTOM (solid shape): 115.08,52.5 115.13,52.45 115.9,52.45 116,52.35 116,52.15 115.49,51.79 116,51.43 116,49.46 115.95,49.4 113.56,49.4 113.29,49.67 113.29,53 113.43,53.14 115.08,53.14
VS_BAT_R on IN4 (solid shape): outline of 164 points within 109.01,50.55 115.52,53.52
WLBT_1V8 on TOP (solid shape): 154.2,79.25 154.2,77.09 154.07,76.96 153.64,76.96 153.08,77.52 152.52,77.52 152.35,77.7 152.35,78.84 152.88,79.38 154.07,79.38
WLBT_3V3 on TOP (solid shape): 152.3,72.04 152.3,69.65 152.04,69.39 151.43,69.39 151.15,69.11 151.15,68.86 151,68.71 148.99,68.71 148.98,68.72 148.12,68.72 147.98,68.86 147.98,71.27 148.1,71.4 150.9,71.4 151.15,71.65 151.15,72.04 151.28,72.16 152.17,72.16
N117237 on BOTTOM (solid shape): 75.69,68.4 75.69,66.96 75.92,66.73 78.61,66.73 80.84,64.49 81.71,64.49 81.78,64.42 81.78,64.24 81.74,64.19 81.71,64.2 81.66,64.2 81.6,64.19 80.64,64.19 78.69,66.14 74.6,66.14 74.47,66.27 74.47,68.4 74.55,68.48 75.61,68.48
N117765 on BOTTOM (solid shape): 82.47,73.23 82.47,72.47 83.08,71.86 83.08,67.44 83.41,67.11 83.41,65.86 83.38,65.84 83.16,65.84 83.13,65.86 83.13,66.65 82.65,67.13 82.65,71.6 82.47,71.78 80.46,71.78 80.11,72.14 80.11,73.23 80.24,73.36 82.34,73.36
N117771 on BOTTOM (solid shape): 79.83,73.23 79.83,69.01 82.6,66.24 82.6,65.86 82.57,65.84 82.37,65.84 82.34,65.86 82.34,66.04 82.17,66.22 81.63,66.22 79.19,68.66 79.19,71.63 78.58,72.24 77.62,72.24 77.52,72.34 77.52,73.26 77.62,73.36 79.7,73.36
N117777 on BOTTOM (solid shape): 75.56,70.82 75.56,70.28 75.74,70.11 78.69,70.11 79.09,69.7 79.09,68.61 81.25,66.45 81.25,65.56 81.53,65.28 81.78,65.28 81.81,65.25 81.81,65.05 81.76,65 81.35,65 77.75,68.61 77.75,69.37 77.54,69.57 75.82,69.57 75.69,69.45 75.69,68.73 75.61,68.66 74.57,68.66 74.47,68.76 74.47,70.84 74.55,70.92 75.46,70.92
N124100 on BOTTOM (solid shape): 86.69,73.05 86.69,71.88 86.66,71.86 86.66,69.8 86.33,69.47 84.73,69.47 84.22,68.96 84.22,65.86 84.2,65.84 84.03,65.84 83.96,65.87 83.93,65.94 83.93,65.98 83.92,66.02 83.92,67.46 83.72,67.67 83.72,69.37 84.45,70.11 86,70.11 86.08,70.18 86.08,71.76 85.59,72.24 84.68,72.24 84.58,72.34 84.58,73.08 84.65,73.15 86.59,73.15
N128385 on IN4 (solid shape): 93.85,59.95 93.85,59.44 93.8,59.39 92.02,59.39 91.97,59.44 91.97,60 92.02,60.05 93.75,60.05
N210426 on BOTTOM (solid shape): 86.23,60.86 86.23,59.87 87.55,58.55 87.98,58.55 88.26,58.27 88.26,57 88.36,56.9 89.48,56.9 89.58,56.8 89.58,55.68 89.51,55.6 87.8,55.6 87.75,55.65 87.75,56.73 87.75,56.79 87.73,56.85 87.73,56.92 87.8,57 87.8,57.86 87.73,57.94 87.63,57.94 85.93,59.63 85.93,60.87 85.95,60.89 86.2,60.89
N308503 on BOTTOM (solid shape): 84.63,60.48 84.63,58.88 85.57,57.94 85.57,57.08 85.75,56.9 86.86,56.9 86.99,56.77 86.99,55.65 86.89,55.55 85.16,55.55 85.04,55.68 85.04,56.95 85.14,57.05 85.14,57.86 84.33,58.67 84.33,60.48 84.36,60.5 84.6,60.5
N513330 on BOTTOM (solid shape): 94.21,64.09 94.21,63.04 94.15,62.99 93.09,62.99 92.81,62.71 89.13,62.71 89.02,62.61 87.26,62.61 87.19,62.68 87.19,62.84 87.22,62.87 88.72,62.87 89.23,63.37 91.92,63.37 92.33,63.78 92.33,64.11 92.38,64.16 94.13,64.16
N513406 on BOTTOM (solid shape): 94.15,65.81 94.15,64.57 93.95,64.37 91.97,64.37 91.89,64.44 89.4,64.44 88.39,63.43 86.76,63.43 86.74,63.45 86.74,63.65 86.79,63.7 86.8,63.7 86.87,63.69 86.95,63.7 87.2,63.7 87.28,63.69 87.35,63.7 88.13,63.7 89.33,64.9 91.87,64.9 92,65.03 92,65.74 92.1,65.84 94.13,65.84
N587789 on IN4 (solid shape): 88.59,73.08 88.59,72.47 88.52,72.39 88.16,72.39 88.08,72.32 88.08,70.31 86.84,69.06 86.84,67.84 85.42,66.42 85.42,65.51 85.34,65.43 85.16,65.61 85.16,66.88 86.33,68.05 86.33,69.29 87.58,70.54 87.58,72.16 87.42,72.32 87.42,73 87.53,73.1 88.57,73.1
N9315085 on BOTTOM (solid shape): 89.46,71.63 89.46,69.82 89.02,69.39 89.02,68.15 87.91,67.03 86.92,67.03 86.23,66.35 86.23,66 86.22,65.95 86.23,65.89 86.23,65.6 86.22,65.54 86.23,65.48 86.18,65.43 86,65.43 85.93,65.51 85.93,65.56 85.92,65.6 85.92,65.9 85.93,65.95 85.92,66 85.92,66.53 86.92,67.53 87.64,67.53 88.57,68.45 88.57,69.32 88.24,69.65 88.24,71.63 88.36,71.76 89.33,71.76
N9316127 on BOTTOM (solid shape): 81.67,63.29 81.73,63.3 81.78,63.25 81.78,63.04 81.73,62.99 81.68,63 81.63,62.99 80.64,62.99 78.71,61.06 75.84,61.06 75.71,60.94 75.71,60.2 75.18,59.67 74.37,59.67 74.29,59.74 74.29,61.57 74.39,61.67 75.33,61.67 75.46,61.55 78.56,61.55 80.31,63.3 81.63,63.3
N9316131 on BOTTOM (solid shape): 81.81,62.05 81.81,61.83 81.78,61.8 81,61.8 78.51,59.31 75.94,59.31 75.74,59.11 75.74,57 75.64,56.9 74.39,56.9 74.29,57 74.29,59.39 74.47,59.56 75.23,59.56 75.56,59.89 78.53,59.89 80.72,62.08 81.78,62.08
N9316135 on BOTTOM (solid shape): 81.81,61.24 81.81,61.06 81.74,60.99 81.71,61 81.66,61 81.6,60.99 81.53,60.99 80.74,60.2 80.74,59.56 78.94,57.76 78.94,57.02 77.77,55.86 75.94,55.86 75.71,55.63 75.71,54.87 75.61,54.76 74.39,54.76 74.29,54.87 74.29,56.67 74.39,56.77 75.69,56.77 75.99,56.47 77.47,56.47 77.57,56.57 77.57,57.23 80.03,59.69 80.03,60 81.33,61.29 81.76,61.29
N9316139 on BOTTOM (solid shape): 82.62,60.48 82.62,59.89 81.61,58.88 81.2,58.88 79.83,57.51 79.83,54.33 79.93,54.23 79.93,53.24 79.85,53.16 78.15,53.16 78.08,53.24 78.08,54.33 78.18,54.43 79.07,54.43 79.22,54.59 79.22,57.86 80.82,59.46 81.58,59.46 82.32,60.2 82.32,60.48 82.34,60.5 82.6,60.5
N9316143 on BOTTOM (solid shape): 83.44,60.48 83.44,58.98 83.26,58.8 83.26,54.64 83.36,54.54 84.48,54.54 84.6,54.41 84.6,53.24 84.53,53.16 82.67,53.16 82.62,53.21 82.62,58.98 83.13,59.49 83.13,59.74 83.13,59.74 83.13,60.38 83.26,60.5 83.41,60.5
N10505050 on TOP (solid shape): 87.37,67.01 87.37,66.19 87.68,65.89 87.68,64.24 87.6,64.16 86.53,64.16 86.43,64.26 86.43,66.96 86.51,67.03 87.35,67.03
N16766415 on IN2 (solid shape): 82.75,61.34 82.75,61.11 82.65,61.01 82.5,61.01 82.04,61.47 81.3,61.47 81.23,61.55 81.23,61.83 81.28,61.88 82.22,61.88
N16794593 on BOTTOM (solid shape): 92.76,70.66 92.76,67.46 92.5,67.21 89.86,67.21 88.36,65.71 88.36,65.38 87.6,64.62 86.76,64.62 86.74,64.64 86.74,64.85 86.76,64.87 87.45,64.87 87.93,65.36 87.93,66.19 89.66,67.92 90.98,67.92 91.08,68.02 91.08,68.48 91.67,69.06 91.67,70.69 91.77,70.79 92.63,70.79
N36538649 on BOTTOM (solid shape): 118.39,65.52 117.91,65.52 117.88,65.56 117.88,67.66 117.89,67.68 118.39,67.68
N36538651 on BOTTOM (solid shape): 120.16,67.67 120.16,65.56 120.12,65.52 119.7,65.52 119.66,65.56 119.66,67.68 120.16,67.68
N39319860 on BOTTOM (solid shape): 33.93,24.16 33.93,23.65 33.68,23.39 32.89,23.39 32.33,22.84 32.33,22.15 32.28,22.1 32.1,22.1 32.05,22.15 32.05,23.42 32.28,23.65 32.28,24.16 32.48,24.36 33.73,24.36
N40413927 on BOTTOM (solid shape): 20.16,35.71 19.17,35.71 19.07,35.82 17.29,35.82 17.29,36.12 19.55,36.12 19.66,36.22 19.66,38 20.16,38
N40413991 on BOTTOM (solid shape): 20.16,33.05 19.66,33.05 19.66,34.82 18.51,34.82 18.49,34.8 17.29,34.8 17.29,35.1 19.02,35.1 19.25,35.33 20.16,35.33
N41708105 on BOTTOM (solid shape): 131.82,75.82 131.82,75.08 131.23,74.49 131.16,74.49 131.14,74.46 131.14,72.42 131.09,72.37 130.4,72.37 130.35,72.42 130.35,74.55 130.28,74.62 130.27,74.62 130.27,75.82 130.4,75.95 131.7,75.95
N41708143 on BOTTOM (solid shape): 133.68,75.82 133.68,73.38 132.64,72.34 131.67,72.34 131.61,72.41 131.61,74.51 132.08,74.98 132.08,75.8 132.2,75.92 133.58,75.92
N41708797 on BOTTOM (solid shape): 128.32,75.72 128.32,74.86 128.63,74.54 128.63,72.4 128.62,72.39 127.86,72.39 126.74,73.51 126.74,75.67 126.84,75.77 128.27,75.77
N41708799 on BOTTOM (solid shape): 130.07,75.67 130.07,74.63 129.89,74.45 129.89,72.41 129.86,72.39 129.16,72.39 129.1,72.44 129.1,74.73 128.55,75.29 128.55,75.64 128.7,75.8 129.94,75.8
N41829139 on BOTTOM (solid shape): 76.86,47.91 77.62,47.91 78.51,47.02 79.02,47.02 79.4,46.64 79.4,46.06 79.24,45.9 79.24,44.7 79.14,44.6 76.73,44.6 76.6,44.73 76.6,45.37 76.35,45.62 74.7,45.62 73.94,46.38 73.3,46.38 73.17,46.51 73.17,48.16 73.3,48.29 76.48,48.29
N41829187 on BOTTOM (solid shape): 80.31,44.02 80.31,40.31 79.47,39.47 71.93,39.47 71.6,39.8 71.6,43.18 71.93,43.51 76.35,43.51 77.16,44.32 80.01,44.32
N41829281 on BOTTOM (solid shape): 81.18,38.25 84.81,38.25 84.84,38.24 84.86,38.2 84.86,38.05 84.84,38.01 84.81,38 83.97,38 83.84,37.87 83.84,37.49 83.46,37.11 80.67,37.11 79.52,35.97 71.9,35.97 71.65,36.22 71.65,38.89 71.9,39.14 80.29,39.14
N42025174 on TOP (solid shape): 157.63,77.22 158.39,77.22 158.52,77.34 159.03,77.34 159.15,77.22 159.15,76.96 158.9,76.71 158.52,76.71 157.88,76.07 157.88,75.44 157.63,75.19 155.66,75.19 155.34,75.34 155.02,75.19 154.38,75.19 154.33,75.24 154.33,76.46 154.45,76.58 155.47,76.58 155.72,76.33 156.36,76.33 156.74,76.71 156.74,77.22 156.87,77.34 157.5,77.34
N42025192 on TOP (solid shape): 162.84,76.33 162.84,75.06 162.2,74.42 158.65,74.42 158.39,74.68 158.39,76.07 158.52,76.2 161.57,76.2 161.82,76.46 162.71,76.46
N42025199 on TOP (solid shape): 164.74,77.98 164.74,74.42 164.36,74.04 163.98,74.04 163.73,74.3 163.73,74.68 163.22,75.19 163.22,77.98 163.34,78.11 164.61,78.11
N42265781 on BOTTOM (solid shape): 14.86,13.9 14.78,13.82 14.78,12.22 14.47,12.22 14.47,13.79 14.32,13.95 14.32,16.44 14.86,16.44
N42265815 on BOTTOM (solid shape): 16.63,16.38 16.63,14.15 16.18,13.69 16.05,13.69 15.8,13.44 15.8,12.22 15.49,12.22 15.49,13.57 16.1,14.17 16.1,16.41 16.61,16.41
N42341593 on TOP (solid shape): 150.39,78.26 150.39,76.61 150.26,76.48 148.74,76.48 148.23,76.99 148.23,78.13 148.49,78.39 150.26,78.39
N42360901 on TOP (solid shape): 56.66,39.09 56.66,37.64 56.23,37.21 55.95,37.21 55.84,37.33 55.84,37.53 56.03,37.72 56.03,39.04 56.11,39.12 56.64,39.12
N42360901 on BOTTOM (solid shape): 56.44,37.67 56.44,37.03 56.31,36.91 56.31,35.37 56.16,35.22 56.01,35.22 56.01,36 55.98,36.04 55.72,36.04 55.69,36.01 55.69,35.22 55.44,35.22 55.41,35.26 55.41,36.07 55.39,36.08 55.39,37.49 55.43,37.52 55.43,37.52 55.78,37.87 56.23,37.87
N42458502 on TOP (solid shape): 151.53,81.69 151.53,80.93 152.04,80.42 152.04,78.77 150.64,78.77 150.52,78.89 150.52,81.69 150.64,81.81 151.41,81.81
N42458518 on TOP (solid shape): 151.91,84.23 151.91,82.96 151.53,82.58 151.53,82.07 151.41,81.94 150.64,81.94 150.52,82.07 150.52,84.35 151.79,84.35
N43057839 on TOP (solid shape): 95.09,55.91 95.09,54.66 95.03,54.6 94.88,54.6 94.71,54.43 94.71,53.6 94.41,53.29 94.31,53.29 94.3,53.29 94.26,53.29 94.2,53.24 94.2,52.45 94.13,52.38 93.34,52.38 93.09,52.63 93.09,55.86 93.32,56.08 94.92,56.08
N43057847 on TOP (solid shape): 97.3,57.76 97.3,56.77 97.08,56.54 94.99,56.54 94.94,56.59 94.94,57.84 95.04,57.94 97.13,57.94

Small or netless copper shapes (teardrops, artwork), in the pictures only: 24 on TOP, 36 on BOTTOM, 1 on IN1, 1 on GND1, 22 on IN2, 19 on IN3, 6 on GND3, 36 on IN4

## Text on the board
Ref Des/Silkscreen Bottom: REV:D | DA0EE6MBAD0 | MODEL:EE6
User.Comments: 20.0x47.0 | 26.0x67.0
Ref Des/Silkscreen Top: DA0EE6MBAD0 | REV:D
GND1: GND1 | 3
GND3: GND3 | 8
User.6: 2 | 5 | 3 | 6 | 4 | 10 | 11 | 9 | 12
User.7: 6
User.8: 2 | 5 | 3 | 6 | 4 | 10 | 11 | 9 | 12
User.12: GND | +V_VCC | +V_VNN | +3V3 | +VDDQ | +1V8S5 | +VSYS
User.26: AGND | GND
